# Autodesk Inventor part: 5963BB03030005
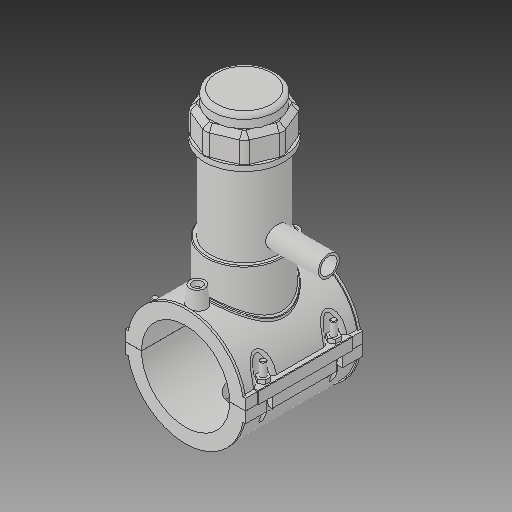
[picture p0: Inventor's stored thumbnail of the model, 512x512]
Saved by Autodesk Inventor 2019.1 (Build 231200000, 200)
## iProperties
Created: 2017-07
Part Number: 5963BB03030005
Material: Generic
Description: PLASSON TAPPING SADDLE 3''IPS x 1 1/2''IPS
Document SubType Name: Modeling
Designer: KIM
Mass: 1712.7 g
Surface Area: 2671.49 cm^2
Volume: 1712.7 cm^3
Density: 1 g/cm^3
Appearance: Default
Author: KIM
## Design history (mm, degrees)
derived "5963B.ipt"
feature "Solid1::5963B.ipt"
feature "Solid2::5963B.ipt"
feature "Solid4::5963B.ipt"
feature "Solid5::5963B.ipt"
tag "TaggingFeature1"
body "Solid1"
body "Solid2"
other parameters: "d0" = 88.7, "d2" = 120.904, "d3" = 22.175, "d4" = 118.11, "d5" = 0, "d6" = 0.1, "d8" = 0, "d19" = 6, "d20" = 6, "d21" = 70.866, "d23" = 0, "d24" = 35.433, "d26" = 0, "d29" = 3, "d30" = 29.56667, "d31" = 6, "d32" = 0, "d33" = 0, "d34" = 0.6, "d40" = 59.9612, "d41" = 79.83, "d43" = 0, "d45" = 0, "d47" = 128.521, "d70" = 15, "d72" = 0, "d73" = 6, "d75" = 5, "d76" = 0, "d77" = 4.435, "d78" = 74.35, "d79" = 15, "d80" = 47.244, "d82" = 5 deg, "d84" = 4, "d85" = 14, "d86" = 0, "d87" = 3, "d88" = 0, "d89" = 1, "d90" = 1, "d91" = 94.488, "d92" = 0, "d93" = 0.5, "d94" = 46.68421, "d96" = 117.6162, "d97" = 2.3622, "d98" = 0, "d102" = 0.887, "d120" = 140 deg, "d121" = 24.228, "d122" = 20 deg, "d123" = 230.62, "d124" = 69.186, "d126" = 0, "d143" = 91.361, "d145" = 20.46923, "d149" = 1.3305, "d150" = 22.51615, "d153" = 118.11, "d154" = 0, "d156" = 57.655, "d157" = 160 deg, "d159" = 5.322, "d161" = 1.3305, "d162" = 70.866, "d163" = 0, "d164" = 44.35, "d167" = 8.87, "d168" = 56.24878, "d170" = 3.2805, "d172" = 0, "d173" = 1, "d175" = 44.35, "d176" = 20 deg, "d177" = 6.209, "d178" = 26.61, "d180" = 0, "d183" = 10.644, "d184" = 4.9672, "d185" = 38.38575, "d186" = 38.38575, "d187" = 57.655, "d188" = 7.983, "d189" = 6.209, "d190" = 0, "d191" = 86.4825, "d193" = 6.1236, "d194" = 4.13385, "d195" = 90 deg, "d197" = 0, "d199" = 0, "d200" = 13.305, "d202" = 0, "d203" = 177.038, "d204" = 75.8385, "d205" = 55.881, "d206" = 67.8555, "d207" = 132.7785, "d208" = 138.08964, "d209" = 164.64534, "d210" = 68.6538, "d211" = 79.83, "d212" = 63.864, "d213" = 48.9816, "d216" = 0, "d217" = 8.87, "d218" = 4.435, "d219" = 0.887, "d222" = 88.7, "d224" = 0, "d230" = 5.322, "d233" = 6, "d236" = 60.452, "d237" = 35.433, "d238" = 6.02433, "d240" = 35.433, "d241" = 35.433, "d242" = 35.433, "d243" = 6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
